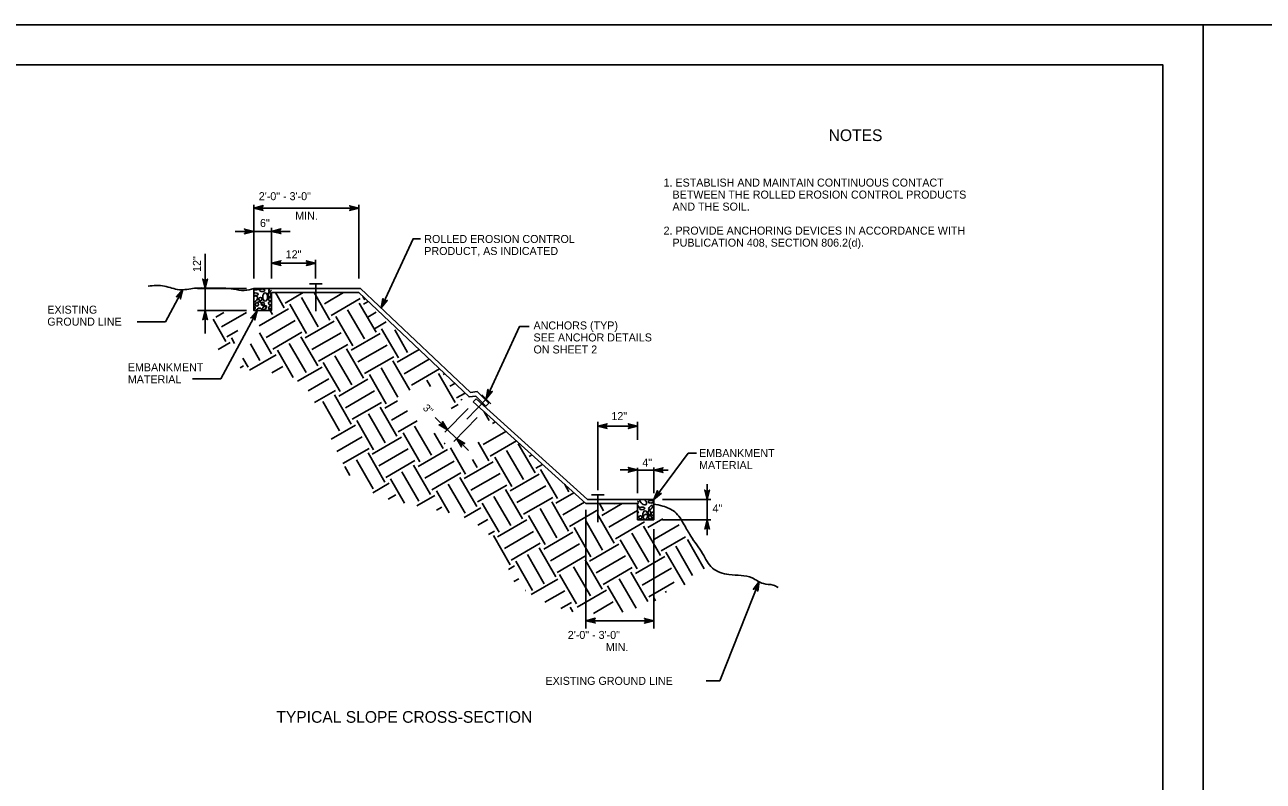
# Model space of a CAD drawing. Extents: x 636462 to 638208, y 299350 to 300538.
# Drawn here: x 636861.7 to 637325.5, y 300255.3 to 300538.4 of the extents above; entities that cross this region are included whole.
import ezdxf

# ---------------------------------------------------------------- set-up
doc = ezdxf.new("R2010")
doc.units = 0
for name, color, linetype in [('1', 7, 'Continuous'), ('Default', 7, 'Continuous'), ('PLT-BNDY', 7, 'Continuous')]:
    doc.layers.add(name, color=color, linetype=linetype)

msp = doc.modelspace()

# ---------------------------------------------------------------- linework, layer by layer
at = {"layer": '1'}
msp.add_lwpolyline([(637287.91, 299959.45), (637287.91, 300523.45), (636501.91, 300523.45), (636501.91, 299959.45), (637287.91, 299959.45), (637287.91, 299985.81), (637087.91, 299985.81), (637087.91, 300050.49), (637287.91, 300050.49), (637287.91, 300079.45), (637087.91, 300079.45), (637087.91, 299959.45), (637166.72, 299959.45), (637166.72, 299985.81), (637166.72, 299959.45), (637243.72, 299959.45), (637243.72, 299985.81), (637243.72, 299973.49), (637287.91, 299973.49)], dxfattribs=at)
at = {"layer": 'Default'}
for p, q in [((636947.43, 300443.41), (636947.43, 300471.08)), ((636947.43, 300469.84), (636986.77, 300469.84)), ((636986.77, 300443.41), (636986.77, 300471.01)), ((636954.09, 300443.41), (636954.09, 300462.41)), ((636970.59, 300443.41), (636970.59, 300450.47)), ((636954.09, 300449.21), (636970.59, 300449.21)), ((636968.26, 300441.46), (636972.99, 300441.46)), ((636970.62, 300441.46), (636970.62, 300431.2)), ((636920.88, 300439.32), (636914.39, 300427.22)), ((636944.68, 300439.77), (636926.32, 300439.77)), ((636955.53, 300438.18), (636958.81, 300432.51)), ((636959.14, 300434.26), (636965.93, 300438.18)), ((636965.23, 300436.32), (636971.54, 300425.4)), ((636969.98, 300438.18), (636975.91, 300427.92)), ((636973.84, 300434.01), (636981.06, 300438.18)), ((636976.37, 300429.65), (636987.28, 300435.95)), ((636987.4, 300439.77), (637028.56, 300400.82)), ((636988.27, 300436.76), (636989.01, 300435.49)), ((636944.68, 300431.52), (636926.32, 300431.52)), ((636949.49, 300425.77), (636960.4, 300432.08)), ((636953.56, 300431.52), (636954.44, 300429.99)), ((636960.87, 300433.8), (636967.17, 300422.88)), ((636982.54, 300431.75), (636988.84, 300420.83)), ((636986.9, 300434.27), (636993.21, 300423.35)), ((636988.5, 300433.84), (636990.27, 300434.87)), ((636914.39, 300427.22), (636903.79, 300427.22)), ((636932.15, 300428.26), (636936.97, 300419.9)), ((636933.18, 300429.02), (636936.2, 300430.76)), ((636948.13, 300430.27), (636935.06, 300405.85)), ((636935.39, 300425.34), (636944.66, 300430.69)), ((636952.01, 300421.41), (636962.92, 300427.71)), ((636966.66, 300421.23), (636977.58, 300427.54)), ((636978.17, 300429.23), (636984.47, 300418.31)), ((636990.11, 300429.04), (636993.19, 300430.82)), ((636992.63, 300424.67), (636997.01, 300427.2)), ((636937.31, 300421.65), (636941.46, 300424.05)), ((636949.55, 300423.14), (636954.07, 300415.32)), ((636954.53, 300417.04), (636965.45, 300423.34)), ((636969.19, 300416.87), (636980.1, 300423.17)), ((636983.89, 300416.62), (636994.8, 300422.92)), ((636995.27, 300424.64), (637001.57, 300413.73)), ((637000.19, 300424.19), (637005.03, 300415.82)), ((636934.13, 300416.91), (636938.57, 300419.47)), ((636939.03, 300421.19), (636940.22, 300419.13)), ((636946.13, 300418.98), (636949.7, 300412.79)), ((636960.7, 300419.15), (636967.01, 300408.23)), ((636965.07, 300421.67), (636971.37, 300410.75)), ((636971.71, 300412.5), (636982.63, 300418.8)), ((636986.41, 300412.25), (636997.33, 300418.56)), ((636943.37, 300413.67), (636945.33, 300410.27)), ((636945.76, 300409.17), (636955.75, 300414.93)), ((636956.33, 300416.62), (636962.21, 300406.45)), ((636977.8, 300414.56), (636984.1, 300403.64)), ((636982.17, 300417.08), (636988.47, 300406.16)), ((636988.93, 300407.89), (636999.85, 300414.19)), ((637001.06, 300412.08), (637009.32, 300416.85)), ((637003.73, 300407.8), (637013.14, 300413.23)), ((636942.29, 300409.97), (636943.61, 300410.73)), ((636954.17, 300408.2), (636958.27, 300410.56)), ((636963.79, 300405.02), (636972.97, 300410.31)), ((636973.43, 300412.04), (636979.73, 300401.12)), ((636995.1, 300409.97), (637001.4, 300399.05)), ((636999.51, 300412.62), (637005.82, 300401.7)), ((637006.54, 300403.59), (637016.96, 300409.61)), ((636935.06, 300405.85), (636924.46, 300405.85)), ((636967.73, 300401.47), (636975.49, 300405.95)), ((636979.23, 300399.47), (636990.15, 300405.78)), ((636990.73, 300407.47), (636997.04, 300396.55)), ((637012.2, 300405.4), (637013.58, 300403.01)), ((637016.57, 300407.93), (637022.87, 300397.01)), ((637018.29, 300407.47), (637018.88, 300407.81)), ((637020.81, 300403.1), (637022.7, 300404.19)), ((636970.18, 300397.06), (636978.01, 300401.58)), ((636977.63, 300399.91), (636983.94, 300388.99)), ((636981.75, 300395.1), (636992.67, 300401.41)), ((637023.33, 300398.73), (637026.52, 300400.57)), ((637028.56, 300400.82), (637031.13, 300401.14)), ((637035.43, 300396.84), (637031.13, 300401.14)), ((637032.8, 300399.91), (637036.17, 300396.59)), ((636973.26, 300397.38), (636979.57, 300386.47)), ((636984.27, 300390.74), (636995.19, 300397.04)), ((636994.73, 300395.32), (637001.03, 300384.4)), ((636996.45, 300394.86), (637001.24, 300397.62)), ((637027.72, 300394.75), (637019, 300385.91)), ((637021.39, 300394.81), (637023.96, 300396.29)), ((637025.13, 300398.32), (637025.36, 300397.92)), ((637034.5, 300398.27), (637027.15, 300390.8)), ((637029.6, 300397.25), (637030.67, 300398.43)), ((637030.67, 300398.43), (637072.41, 300360.77)), ((637034.36, 300395.66), (637035.43, 300396.84)), ((636985.99, 300390.28), (636992.3, 300379.36)), ((636990.36, 300392.8), (636996.66, 300381.88)), ((636998.97, 300390.49), (637004.93, 300393.93)), ((637001.49, 300386.12), (637008.62, 300390.24)), ((637015.35, 300391.37), (637027.87, 300379.04)), ((637031.09, 300391.43), (637022.28, 300382.49)), ((637033.71, 300393.54), (637035.61, 300390.25)), ((637036.78, 300389.13), (637037.89, 300389.77)), ((637076.24, 300364.21), (637076.24, 300389.86)), ((637091.15, 300383.03), (637091.15, 300389.86)), ((636976.44, 300383.3), (636985.53, 300388.55)), ((637003.3, 300385.71), (637009.6, 300374.79)), ((637007.66, 300388.23), (637013.97, 300377.31)), ((637015.03, 300385.57), (637018.34, 300379.83)), ((637033.37, 300381.34), (637041.83, 300386.22)), ((636978.48, 300378.66), (636988.05, 300384.19)), ((636991.79, 300377.71), (637002.71, 300384.02)), ((637018.67, 300381.58), (637019.08, 300381.82)), ((637031.39, 300382.24), (637035.43, 300375.25)), ((637035.89, 300376.97), (637045.76, 300382.67)), ((637046.43, 300381.6), (637052.74, 300370.68)), ((636980.77, 300374.16), (636990.57, 300379.82)), ((636985.83, 300375.62), (636992.13, 300364.7)), ((636990.2, 300378.15), (636996.5, 300367.23)), ((636994.31, 300373.34), (637005.23, 300379.65)), ((637009.01, 300373.1), (637019.93, 300379.4)), ((637021.03, 300380.01), (637026.7, 300370.21)), ((637029.33, 300375.74), (637031.06, 300372.73)), ((637037.7, 300376.56), (637044, 300365.64)), ((637042.06, 300379.08), (637048.37, 300368.16)), ((637050.55, 300376.8), (637051.6, 300377.41)), ((637097.18, 300360.77), (637110.07, 300378.13)), ((637113.24, 300378.13), (637110.07, 300378.13)), ((636981.46, 300373.1), (636983.41, 300369.73)), ((636996.83, 300368.98), (637007.75, 300375.28)), ((637002.92, 300371.04), (637009.23, 300360.12)), ((637007.29, 300373.56), (637013.6, 300362.64)), ((637011.53, 300368.73), (637022.45, 300375.03)), ((637026.19, 300368.56), (637037.11, 300374.86)), ((637053.07, 300372.43), (637055.54, 300373.85)), ((637054.79, 300371.97), (637061.1, 300361.05)), ((637091.15, 300363.09), (637091.15, 300372.59)), ((637097.18, 300363.09), (637097.18, 300372.75)), ((636991.96, 300363.25), (636998.09, 300366.79)), ((636998.56, 300368.52), (637003.86, 300359.34)), ((637014.06, 300364.36), (637024.97, 300370.67)), ((637020.23, 300366.47), (637026.53, 300355.55)), ((637024.6, 300368.99), (637030.9, 300358.07)), ((637028.71, 300364.19), (637039.63, 300370.5)), ((637043.41, 300363.94), (637054.33, 300370.25)), ((637063.87, 300366.33), (637065.46, 300363.57)), ((636997.8, 300360.8), (637000.62, 300362.43)), ((637008.46, 300358.32), (637015.27, 300362.26)), ((637015.86, 300363.95), (637020.6, 300355.74)), ((637031.23, 300359.82), (637042.15, 300366.13)), ((637037.32, 300361.88), (637043.63, 300350.97)), ((637041.69, 300364.41), (637048, 300353.49)), ((637045.94, 300359.58), (637056.85, 300365.88)), ((637060.59, 300359.41), (637067.27, 300363.26)), ((637073.88, 300362.49), (637078.61, 300362.49)), ((637076.24, 300362.49), (637076.24, 300352.22)), ((637015.84, 300356.76), (637017.8, 300357.89)), ((637026.25, 300354.03), (637032.49, 300357.64)), ((637032.96, 300359.36), (637039.26, 300348.44)), ((637048.46, 300355.21), (637059.37, 300361.51)), ((637054.63, 300357.32), (637060.93, 300346.4)), ((637059, 300359.84), (637065.3, 300348.92)), ((637063.11, 300355.04), (637071.21, 300359.71)), ((637076.84, 300359.18), (637078.4, 300356.48)), ((637077.81, 300354.79), (637085.41, 300359.18)), ((637082.67, 300359.18), (637082.77, 300359.01)), ((637100.52, 300360.77), (637118.56, 300360.77)), ((637031.29, 300351.12), (637035.02, 300353.27)), ((637038.75, 300346.8), (637049.67, 300353.1)), ((637050.26, 300354.8), (637056.56, 300343.88)), ((637065.63, 300350.67), (637076.55, 300356.98)), ((637071.72, 300352.73), (637078.03, 300341.81)), ((637071.8, 300312.43), (637071.8, 300356.83)), ((637076.09, 300355.25), (637082.4, 300344.34)), ((637080.34, 300350.43), (637091.15, 300356.67)), ((637082.86, 300346.06), (637093.77, 300352.36)), ((637094.99, 300350.25), (637100.58, 300353.48)), ((637100.52, 300353.15), (637118.56, 300353.15)), ((637035.3, 300347.61), (637037.54, 300348.91)), ((637041.28, 300342.43), (637052.2, 300348.73)), ((637055.98, 300342.18), (637066.9, 300348.49)), ((637067.36, 300350.21), (637073.66, 300339.29)), ((637089.03, 300348.16), (637095.33, 300337.24)), ((637093.4, 300350.69), (637099.7, 300339.77)), ((637097.18, 300312.43), (637097.18, 300349.63)), ((637097.51, 300345.88), (637106.74, 300351.21)), ((637037.16, 300347.23), (637043.46, 300336.31)), ((637043.8, 300338.06), (637054.72, 300344.37)), ((637058.5, 300337.82), (637069.42, 300344.12)), ((637073.15, 300337.65), (637084.07, 300343.95)), ((637084.66, 300345.64), (637090.96, 300334.72)), ((637100.03, 300341.52), (637109.13, 300346.77)), ((637105.42, 300343.22), (637111.73, 300332.3)), ((637109.79, 300345.74), (637116.09, 300334.82)), ((637049.89, 300340.12), (637056.19, 300329.21)), ((637054.26, 300342.65), (637060.56, 300331.73)), ((637061.02, 300333.45), (637071.94, 300339.75)), ((637075.68, 300333.28), (637086.6, 300339.58)), ((637090.38, 300333.03), (637101.3, 300339.33)), ((637101.76, 300341.06), (637108.83, 300328.81)), ((637042.8, 300334.58), (637045.06, 300335.88)), ((637045.52, 300337.6), (637051.82, 300326.68)), ((637067.19, 300335.56), (637073.5, 300324.64)), ((637071.56, 300338.08), (637077.86, 300327.16)), ((637078.2, 300328.91), (637089.12, 300335.21)), ((637092.9, 300328.66), (637103.82, 300334.97)), ((637044.84, 300330.02), (637046.67, 300331.08)), ((637051.32, 300325.14), (637061.33, 300330.91)), ((637061.91, 300332.6), (637068.22, 300321.68)), ((637084.29, 300330.97), (637090.59, 300320.05)), ((637088.66, 300333.49), (637094.96, 300322.57)), ((637095.42, 300324.3), (637104.87, 300329.75)), ((637136.64, 300330.02), (637121.93, 300292.88)), ((637049.09, 300326.65), (637049.19, 300326.71)), ((637056.41, 300322.25), (637063.85, 300326.54)), ((637068.54, 300320.42), (637079.46, 300326.73)), ((637079.92, 300328.45), (637085.64, 300318.54)), ((637101.59, 300326.4), (637101.86, 300325.94)), ((637062.37, 300319.86), (637066.37, 300322.17)), ((637065.91, 300320.45), (637066.92, 300318.71)), ((637074.59, 300318.09), (637081.98, 300322.36)), ((637097.22, 300323.88), (637097.83, 300322.84)), ((637071.8, 300315.36), (637097.18, 300315.36)), ((637121.93, 300292.88), (637116.78, 300292.88))]:
    msp.add_line(p, q, dxfattribs=at)
for points in [[(636950.66, 300469.2), (636950.93, 300468.98), (636947.43, 300469.84), (636950.66, 300469.2), (636950.47, 300469.58), (636947.43, 300469.84), (636950.46, 300470.1), (636950.64, 300470.48), (636947.43, 300469.84), (636950.92, 300470.73), (636950.64, 300470.48)], [(636983.54, 300470.48), (636983.27, 300470.7), (636986.77, 300469.84), (636983.54, 300470.48), (636983.74, 300470.11), (636986.77, 300469.84), (636983.74, 300469.58), (636983.56, 300469.21), (636986.77, 300469.84), (636983.28, 300468.95), (636983.56, 300469.21)], [(636954.09, 300461.12), (636940.43, 300461.12)], [(636944.2, 300461.75), (636943.93, 300461.98), (636947.43, 300461.12), (636944.2, 300461.75), (636944.4, 300461.38), (636947.43, 300461.12), (636944.4, 300460.86), (636944.22, 300460.48), (636947.43, 300461.12), (636943.94, 300460.23), (636944.22, 300460.48)], [(636957.33, 300460.48), (636957.59, 300460.26), (636954.09, 300461.12), (636957.33, 300460.48), (636957.13, 300460.85), (636954.09, 300461.12), (636957.12, 300461.38), (636957.31, 300461.75), (636954.09, 300461.12), (636957.59, 300462), (636957.31, 300461.75)], [(636954.09, 300461.12), (636961.05, 300461.12)], [(636995.17, 300432.42), (637007.07, 300458.32), (637009.83, 300458.32)], [(636929.17, 300439.77), (636929.17, 300452.71)], [(636957.33, 300448.58), (636957.59, 300448.35), (636954.09, 300449.21), (636957.33, 300448.58), (636957.13, 300448.95), (636954.09, 300449.21), (636957.12, 300449.47), (636957.31, 300449.85), (636954.09, 300449.21), (636957.59, 300450.1), (636957.31, 300449.85)], [(636967.36, 300449.85), (636967.09, 300450.07), (636970.59, 300449.21), (636967.36, 300449.85), (636967.56, 300449.48), (636970.59, 300449.21), (636967.56, 300448.95), (636967.38, 300448.58), (636970.59, 300449.21), (636967.1, 300448.33), (636967.38, 300448.58)], [(636929.8, 300443), (636930.03, 300443.27), (636929.17, 300439.77), (636929.8, 300443), (636929.43, 300442.8), (636929.17, 300439.77), (636928.91, 300442.8), (636928.53, 300442.98), (636929.17, 300439.77), (636928.28, 300443.26), (636928.53, 300442.98)], [(636918.79, 300436.78), (636918.46, 300436.65), (636920.88, 300439.32), (636918.79, 300436.78), (636919.21, 300436.78), (636920.88, 300439.32), (636919.67, 300436.53), (636919.92, 300436.19), (636920.88, 300439.32), (636920.01, 300435.83), (636919.92, 300436.19)], [(636929.17, 300439.65), (636929.17, 300422.87)], [(636987.4, 300439.77), (636947.43, 300439.77), (636947.43, 300431.52), (636954.09, 300431.52), (636954.09, 300438.18), (636986.77, 300438.18), (637028.02, 300399.15), (637030.56, 300399.47), (637034.36, 300395.66)], [(636997.09, 300435.1), (636997.4, 300435.25), (636995.17, 300432.42), (636997.09, 300435.1), (636996.66, 300435.08), (636995.17, 300432.42), (636996.19, 300435.29), (636995.92, 300435.61), (636995.17, 300432.42), (636995.8, 300435.97), (636995.92, 300435.61)], [(636928.53, 300428.28), (636928.31, 300428.02), (636929.17, 300431.52), (636928.53, 300428.28), (636928.9, 300428.48), (636929.17, 300431.52), (636929.43, 300428.49), (636929.8, 300428.3), (636929.17, 300431.52), (636930.05, 300428.02), (636929.8, 300428.3)], [(636946.62, 300428.82), (636946.29, 300428.69), (636948.72, 300431.36), (636946.62, 300428.82), (636947.04, 300428.82), (636948.72, 300431.36), (636947.5, 300428.57), (636947.75, 300428.23), (636948.72, 300431.36), (636947.83, 300427.87), (636947.75, 300428.23)], [(637035.21, 300399.98), (637046.95, 300425.54), (637050.6, 300425.54)], [(637036.41, 300401.06), (637036.73, 300401.21), (637034.48, 300398.39), (637036.41, 300401.06), (637035.99, 300401.03), (637034.48, 300398.39), (637035.51, 300401.25), (637035.25, 300401.57), (637034.48, 300398.39), (637035.13, 300401.93), (637035.25, 300401.57)], [(637029.6, 300397.25), (637071.8, 300359.18), (637091.15, 300359.18), (637091.15, 300353.15), (637097.18, 300353.15), (637097.18, 300360.77), (637072.41, 300360.77)], [(637018.06, 300389.57), (637018.03, 300389.91), (637019.94, 300386.85), (637018.06, 300389.57), (637017.95, 300389.16), (637019.94, 300386.85), (637017.58, 300388.78), (637017.19, 300388.64), (637019.94, 300386.85), (637016.81, 300388.66), (637017.19, 300388.64)], [(637079.47, 300387.59), (637079.74, 300387.36), (637076.24, 300388.22), (637079.47, 300387.59), (637079.28, 300387.96), (637076.24, 300388.22), (637079.27, 300388.48), (637079.45, 300388.86), (637076.24, 300388.22), (637079.74, 300389.11), (637079.45, 300388.86)], [(637091.15, 300388.22), (637076.24, 300388.22)], [(637087.92, 300388.86), (637087.65, 300389.08), (637091.15, 300388.22), (637087.92, 300388.86), (637088.12, 300388.49), (637091.15, 300388.22), (637088.12, 300387.96), (637087.94, 300387.59), (637091.15, 300388.22), (637087.66, 300387.34), (637087.94, 300387.59)], [(637025.13, 300380.79), (637025.17, 300380.44), (637023.31, 300383.53), (637025.13, 300380.79), (637025.26, 300381.19), (637023.31, 300383.53), (637025.63, 300381.57), (637026.02, 300381.7), (637023.31, 300383.53), (637026.4, 300381.68), (637026.02, 300381.7)], [(637091.15, 300371.85), (637084.63, 300371.85)], [(637087.92, 300372.48), (637087.65, 300372.71), (637091.15, 300371.85), (637087.92, 300372.48), (637088.12, 300372.11), (637091.15, 300371.85), (637088.12, 300371.59), (637087.94, 300371.21), (637091.15, 300371.85), (637087.66, 300370.96), (637087.94, 300371.21)], [(637091.15, 300371.75), (637102.58, 300371.75)], [(637100.41, 300371.11), (637100.68, 300370.89), (637097.18, 300371.75), (637100.41, 300371.11), (637100.22, 300371.48), (637097.18, 300371.75), (637100.21, 300372.01), (637100.39, 300372.38), (637097.18, 300371.75), (637100.68, 300372.63), (637100.39, 300372.38)], [(637117.21, 300347.41), (637117.21, 300366.42)], [(637099.66, 300362.94), (637100, 300363.02), (637097.18, 300360.77), (637099.66, 300362.94), (637099.24, 300363.01), (637097.18, 300360.77), (637098.82, 300363.33), (637098.63, 300363.7), (637097.18, 300360.77), (637098.61, 300364.08), (637098.63, 300363.7)], [(637117.85, 300364), (637118.07, 300364.27), (637117.21, 300360.77), (637117.85, 300364), (637117.48, 300363.8), (637117.21, 300360.77), (637116.95, 300363.79), (637116.58, 300363.98), (637117.21, 300360.77), (637116.32, 300364.26), (637116.58, 300363.98)], [(637116.57, 300349.92), (637116.35, 300349.65), (637117.21, 300353.15), (637116.57, 300349.92), (637116.95, 300350.12), (637117.21, 300353.15), (637117.47, 300350.12), (637117.85, 300349.94), (637117.21, 300353.15), (637118.1, 300349.66), (637117.85, 300349.94)], [(637134.85, 300327.26), (637134.54, 300327.1), (637136.64, 300330.02), (637134.85, 300327.26), (637135.27, 300327.31), (637136.64, 300330.02), (637135.76, 300327.12), (637136.04, 300326.81), (637136.64, 300330.02), (637136.17, 300326.45), (637136.04, 300326.81)], [(637075.03, 300314.72), (637075.3, 300314.5), (637071.8, 300315.36), (637075.03, 300314.72), (637074.84, 300315.09), (637071.8, 300315.36), (637074.83, 300315.62), (637075.01, 300315.99), (637071.8, 300315.36), (637075.3, 300316.25), (637075.01, 300315.99)], [(637093.95, 300316), (637093.68, 300316.22), (637097.18, 300315.36), (637093.95, 300316), (637094.15, 300315.62), (637097.18, 300315.36), (637094.15, 300315.1), (637093.97, 300314.72), (637097.18, 300315.36), (637093.69, 300314.47), (637093.97, 300314.72)]]:
    msp.add_lwpolyline(points, dxfattribs=at)
for centre in [(636949.91, 300435.75), (636948.57, 300433.75), (636950.78, 300433.96), (637092.2, 300354.06), (637095.85, 300354.03)]:
    msp.add_circle(centre, 0.607, dxfattribs=at)
for centre, radius, start, end in [((636953.55, 300435.73), 0.607, 26.488, 333.512), ((636954.55, 300437.12), 0.607, 138.9194, 221.0806), ((636949.51, 300431.26), 1.1, 13.5097, 166.4903), ((636949.45, 300433.62), 1.1, 13.0401, 127.2116), ((636951.6, 300434.11), 1.1, 193.0401, 307.2116), ((636951.89, 300430.96), 0.607, 66.2736, 113.7264), ((636953.59, 300434.24), 0.607, 34.7009, 325.2991), ((637090.87, 300359.66), 0.607, 298.443, 61.557), ((637097.71, 300358.93), 0.607, 149.4248, 210.5752), ((637094.37, 300354.1), 1.1, 62.8174, 176.9889), ((637095.37, 300356.06), 1.1, 242.8174, 356.9889), ((637095.89, 300352.54), 0.607, 89.1768, 90.8232), ((637096.85, 300355.43), 0.607, 56.7002, 303.2998)]:
    msp.add_arc(centre, radius, start, end, dxfattribs=at)
for centre, major_axis, ratio, start_param, end_param in [((636948.18, 300437.57), (-0.972, 0), 0.5, 0.688105, 5.59508), ((636947.54, 300435.64), (-1.12, -1.12), 0.565936, 0.973254, 4.27994), ((636948.41, 300439.68), (-0.972, 0), 0.5, 0, 3.328834), ((636948.41, 300439.68), (-0.972, 0), 0.5, 6.095944, 6.283175), ((636950.56, 300439.07), (-0.972, 0), 0.5, 0, 6.283175), ((636951.69, 300436.54), (0, -1.58), 0.565936, 0, 6.283175), ((636953.23, 300437.39), (0, 0.972), 0.5, 0, 6.283175), ((636953.76, 300439.39), (0.687, 0.687), 0.5, 1.526333, 4.701865), ((636947.22, 300432.81), (-0.687, 0.687), 0.5, 2.309022, 4.901459), ((636951.46, 300432.51), (-0.687, -0.687), 0.5, 0, 6.283175), ((636953.75, 300432.78), (0.687, 0.687), 0.5, 0.65006, 4.70583), ((637090.71, 300357.98), (-0.972, 0), 0.5, 2.049072, 4.234113), ((637093.21, 300360.02), (1.12, -1.12), 0.565936, 3.5768, 6.283175), ((637092.85, 300357.38), (-0.972, 0), 0.5, 0, 6.283175), ((637093.21, 300360.02), (1.12, -1.12), 0.565936, 0, 1.676394), ((637096.11, 300359.87), (-0.972, 0), 0.5, 0, 6.283175), ((637096.05, 300357.7), (0.687, 0.687), 0.5, 0, 6.283175), ((637090.48, 300355.88), (-0.972, 0), 0.5, 2.339071, 3.944115), ((637093.99, 300354.85), (0, -1.58), 0.565936, 0, 6.283175), ((637095.52, 300355.69), (0, 0.972), 0.5, 0, 6.283175), ((637097.34, 300353.56), (0, 0.972), 0.5, 0.332575, 2.01004)]:
    msp.add_ellipse(centre, major_axis=major_axis, ratio=ratio, start_param=start_param, end_param=end_param, dxfattribs=at)
for points in [[(636947.43, 300439.77), (636943.82, 300438.97), (636939.88, 300439.52), (636932, 300439.8), (636925.22, 300439.8), (636919.54, 300439.25), (636913.95, 300440.62), (636907.81, 300440.62)], [(637097.18, 300358.97), (637100.6, 300358.29), (637105.05, 300356.06), (637108.63, 300351.22), (637111.05, 300347.06), (637115.51, 300340.47), (637119.19, 300335.05), (637125.38, 300332.63), (637134.09, 300331.37), (637138.25, 300329.24), (637141.93, 300328.66), (637143.77, 300327.78)]]:
    msp.add_spline(points, degree=3, dxfattribs=at)
at = {"layer": 'PLT-BNDY'}
for points in [[(636461.91, 300538.45), (637302.91, 300538.45), (637302.91, 299944.45), (636461.91, 299944.45)], [(637302.91, 300538.45), (638143.91, 300538.45), (638143.91, 299944.45), (637302.91, 299944.45)]]:
    msp.add_lwpolyline(points, close=True, dxfattribs=at)

# ---------------------------------------------------------------- texts
at = {"layer": 'Default'}
for s, height, p in [('NOTES', 4.372, (637162.7, 300494.91)), ('1. ESTABLISH AND MAINTAIN CONTINUOUS CONTACT', 2.998, (637100.88, 300477.87)), ('2\'-0" - 3\'-0"', 2.998, (636949.28, 300472.78)), ('   BETWEEN THE ROLLED EROSION CONTROL PRODUCTS', 2.998, (637100.88, 300473.38)), ('MIN.', 2.998, (636962.95, 300465.45)), ('   AND THE SOIL.', 2.998, (637100.88, 300468.88)), ('6"', 2.998, (636949.74, 300462.74)), ('ROLLED EROSION CONTROL', 2.998, (637011.27, 300456.76)), ('2. PROVIDE ANCHORING DEVICES IN ACCORDANCE WITH', 2.998, (637100.88, 300459.89)), ('PRODUCT, AS INDICATED', 2.998, (637011.27, 300452.26)), ('   PUBLICATION 408, SECTION 806.2(d).', 2.998, (637100.88, 300455.39)), ('12"', 2.998, (636959.36, 300451.01)), ('EXISTING', 2.998, (636870.09, 300430.3)), ('GROUND LINE', 2.998, (636870.09, 300425.81)), ('ANCHORS (TYP)', 2.998, (637052.18, 300424.39)), ('SEE ANCHOR DETAILS', 2.998, (637052.18, 300419.9)), ('ON SHEET 2', 2.998, (637052.18, 300415.4)), ('EMBANKMENT', 2.998, (636900.25, 300408.73)), ('MATERIAL', 2.998, (636900.25, 300404.23)), ('12"', 2.998, (637081.35, 300390.45)), ('4"', 2.998, (637092.93, 300373.07)), ('EMBANKMENT', 2.998, (637114.18, 300376.62)), ('MATERIAL', 2.998, (637114.18, 300372.12)), ('4"', 2.998, (637119.22, 300355.89)), ('2\'-0" - 3\'-0"', 2.998, (637065.01, 300308.53)), ('MIN.', 2.998, (637079.25, 300303.96)), ('EXISTING GROUND LINE', 2.998, (637056.67, 300291.33)), ('TYPICAL SLOPE CROSS-SECTION', 4.3721, (636955.87, 300277.14))]:
    msp.add_text(s, height=height, dxfattribs=at).set_placement(p)
for s, height, rotation, p in [('12"', 2.998, 90, (636927.62, 300445.93)), ('3"', 2.835, 315.4374, (637010.49, 300394.73))]:
    msp.add_text(s, height=height, rotation=rotation, dxfattribs=at).set_placement(p)

doc.saveas('drawing.dxf')
